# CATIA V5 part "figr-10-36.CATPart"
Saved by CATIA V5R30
Part number: Part1
Bounding box of the stored display mesh (mm): x -85.282 to 128.744, y -7.97 to 191.596, z 0 to 148.964
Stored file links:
  D:\PROJECTS\CATIA V56R 2020\Resources\Parts File\c10_catia_v5_6r2020_prt\figr-10-36.CATPart
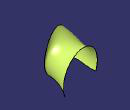
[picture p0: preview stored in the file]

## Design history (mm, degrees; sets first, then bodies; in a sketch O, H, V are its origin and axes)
Set1
  Sketch1 on xy-plane, origin (0, 0, 0), H (1, 0, 0), V (0, 1, 0)
    spline S1 through (-60, 0) (-70, 70) (-70, 170) (-80, 190)
  Sketch2 on yz-plane, origin (0, 0, 0), H (0, 1, 0), V (0, 0, 1)
    spline S1 through (0, 170) (100, 120) (180, 150)
  Sketch3 on xy-plane, origin (0, 0, 0), H (1, 0, 0), V (0, 1, 0)
    spline S1 through (70, 0) (70, 80) (120, 190)
  Sweep1: type Circle, Guide (Sketch1; Sketch2; Sketch3)
Body1 (main body)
